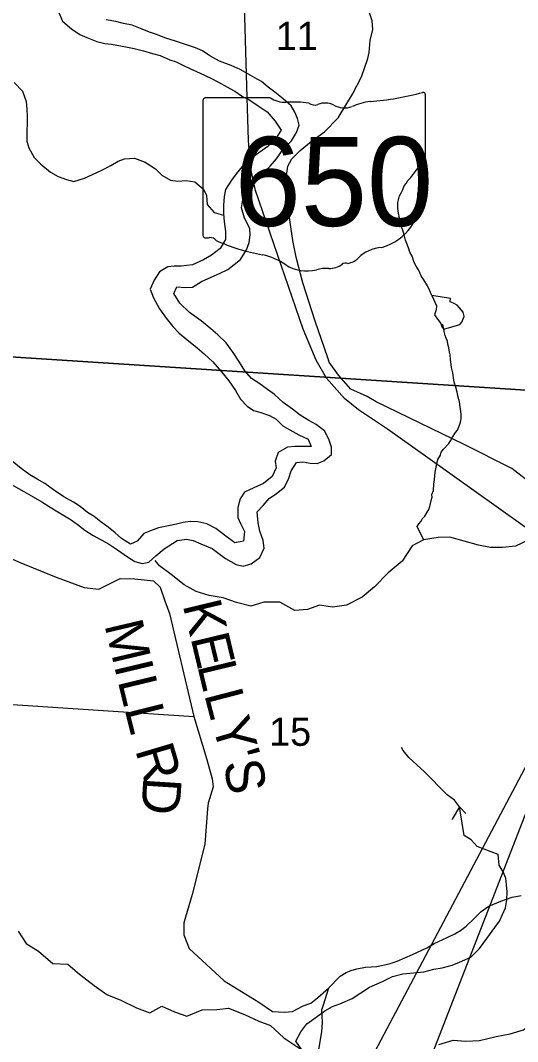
# Model space of a CAD drawing. Extents: x 0 to 34, y 0 to 22.
# Drawn here: x 4.467 to 5.204, y 16.547 to 18.059 of the extents above; entities that cross this region are included whole.
import ezdxf

# ---------------------------------------------------------------- set-up
doc = ezdxf.new("R2010")
doc.units = 0
for name, color, linetype in [('GM_X_County_Road', 7, 'Continuous'), ('GM_X_County_Road_Text', 7, 'Continuous'), ('GM_X_Minor_Lake', 7, 'Continuous'), ('GM_X_Minor_River', 7, 'Continuous'), ('GM_X_Rail_Line', 7, 'Continuous'), ('GM_X_Section', 7, 'Continuous'), ('GM_X_Section_Text', 7, 'Continuous'), ('GM_X_State_Location', 7, 'Continuous'), ('GM_X_State_Route', 7, 'Continuous'), ('GM_X_State_Shield', 7, 'Continuous'), ('GM_X_Township_Road', 7, 'Continuous'), ('SH_Text', 7, 'Continuous')]:
    doc.layers.add(name, color=color, linetype=linetype)

msp = doc.modelspace()

# ---------------------------------------------------------------- linework, layer by layer
at = {"layer": 'GM_X_County_Road'}
for points in [[(4.4211, 17.2763), (4.4677, 17.2559), (4.52, 17.2346), (4.5613, 17.2194), (4.5829, 17.2172), (4.6147, 17.2327), (4.6367, 17.2323), (4.664, 17.2294), (4.6741, 17.2201), (4.681, 17.1999), (4.6879, 17.181), (4.7218, 17.037)], [(4.7218, 17.037), (4.7239, 17.0284), (4.7432, 16.9648), (4.7511, 16.9362), (4.7525, 16.9242), (4.7451, 16.9004), (4.744, 16.892), (4.74, 16.8395), (4.7214, 16.765), (4.7091, 16.723), (4.7092, 16.7052), (4.7168, 16.685), (4.7689, 16.637), (4.82, 16.6055), (4.8404, 16.5917), (4.8582, 16.5905), (4.8701, 16.5915), (4.8858, 16.6), (4.8972, 16.604), (4.9072, 16.6121), (4.9234, 16.6264), (4.9408, 16.6439), (4.9497, 16.6494), (4.957, 16.6525), (4.9656, 16.6551), (4.9782, 16.6575), (4.995, 16.6585), (5.0134, 16.6623), (5.0251, 16.6664), (5.048, 16.676), (5.069, 16.686), (5.0799, 16.6925), (5.0992, 16.7015), (5.1108, 16.7066), (5.1192, 16.7118), (5.1273, 16.7181), (5.1394, 16.7296), (5.1496, 16.7396), (5.1608, 16.7478), (5.1787, 16.7551), (5.1954, 16.7608), (5.2091, 16.7635)]]:
    msp.add_lwpolyline(points, dxfattribs=at)
at = {"layer": 'GM_X_Minor_Lake'}
for points in [[(5.0764, 17.6517), (5.0834, 17.6367), (5.083, 17.6306), (5.0803, 17.6235), (5.0848, 17.617), (5.0897, 17.6105), (5.0915, 17.6055), (5.0942, 17.6022)], [(5.0942, 17.6022), (5.1181, 17.6088), (5.1211, 17.6122), (5.1246, 17.6209), (5.1231, 17.627), (5.1175, 17.6334), (5.1141, 17.6376), (5.1088, 17.6407), (5.1035, 17.6423), (5.1035, 17.643), (5.104, 17.6476), (5.0764, 17.6517)]]:
    msp.add_lwpolyline(points, dxfattribs=at)
at = {"layer": 'GM_X_Minor_River'}
for points in [[(4.5238, 18.0712), (4.5294, 18.0579), (4.5424, 18.0468), (4.5549, 18.0384), (4.5652, 18.0339)], [(4.8178, 17.3315), (4.8265, 17.341), (4.8353, 17.3512), (4.8463, 17.3588), (4.8584, 17.3683), (4.8645, 17.3816), (4.8683, 17.3923), (4.876, 17.4044), (4.8855, 17.4056), (4.8961, 17.4036), (4.9064, 17.4029), (4.9166, 17.4071), (4.928, 17.4165), (4.9277, 17.4272), (4.9246, 17.4378), (4.9178, 17.4511), (4.9053, 17.461), (4.8942, 17.4667), (4.8813, 17.4747), (4.8703, 17.4835), (4.8563, 17.4934), (4.8433, 17.5052), (4.8331, 17.5128), (4.8202, 17.5223), (4.8091, 17.5288), (4.7993, 17.5406), (4.7917, 17.5531), (4.7822, 17.5676), (4.7716, 17.5816), (4.7594, 17.5938), (4.7491, 17.6026), (4.7347, 17.6144), (4.7176, 17.6269), (4.7032, 17.6406), (4.6941, 17.6547), (4.6986, 17.6646), (4.7108, 17.6638), (4.7218, 17.6642), (4.7351, 17.6725), (4.7496, 17.679), (4.7621, 17.6843), (4.7743, 17.6903), (4.7929, 17.7052), (4.8021, 17.7196), (4.8059, 17.7302), (4.8074, 17.7416), (4.8066, 17.7511), (4.799, 17.7663), (4.7945, 17.7816), (4.7968, 17.7964), (4.8025, 17.8089), (4.8105, 17.8184), (4.8223, 17.8294), (4.8371, 17.8435), (4.8462, 17.8545), (4.8561, 17.8685), (4.8687, 17.8811), (4.8759, 17.8932), (4.8797, 17.9039), (4.8774, 17.9138), (4.8736, 17.9233), (4.868, 17.9328), (4.8562, 17.943), (4.844, 17.9529), (4.8341, 17.9602), (4.8243, 17.9689), (4.8144, 17.9743), (4.8041, 17.9803), (4.7927, 17.9864), (4.7791, 17.9925), (4.762, 17.999), (4.7475, 18.007), (4.7365, 18.0142), (4.7262, 18.0188), (4.7114, 18.0234), (4.6966, 18.0283), (4.6825, 18.0329), (4.6685, 18.0382), (4.6582, 18.042), (4.6472, 18.0462), (4.6324, 18.052), (4.6199, 18.0546), (4.6081, 18.0577), (4.594, 18.0603)], [(4.5652, 18.0339), (4.5804, 18.0278), (4.5921, 18.0251), (4.602, 18.024), (4.6153, 18.0217), (4.6256, 18.0198), (4.6355, 18.0175), (4.6495, 18.014), (4.6624, 18.0102), (4.6742, 18.0072), (4.6883, 18.0007), (4.6978, 17.9977), (4.7084, 17.9927), (4.7179, 17.9878), (4.7331, 17.9813), (4.7491, 17.9737), (4.7605, 17.968), (4.773, 17.9611), (4.7848, 17.9546), (4.7958, 17.9466), (4.8053, 17.9421), (4.8194, 17.9326), (4.8323, 17.9238), (4.8444, 17.9101), (4.8535, 17.8968), (4.8467, 17.8869), (4.8334, 17.8725), (4.8204, 17.863), (4.8083, 17.8546), (4.7953, 17.8429), (4.7866, 17.8322), (4.7798, 17.8227), (4.771, 17.8091), (4.7687, 17.7984), (4.7676, 17.7855), (4.7676, 17.7726), (4.7687, 17.7615), (4.771, 17.7467), (4.7706, 17.7349), (4.763, 17.7216), (4.75, 17.7118), (4.7382, 17.7046), (4.7219, 17.6974), (4.7052, 17.6951), (4.6949, 17.6951), (4.6854, 17.6943), (4.6729, 17.6868), (4.6649, 17.6746), (4.6592, 17.6613), (4.6641, 17.6484), (4.6728, 17.632), (4.6827, 17.6183), (4.6926, 17.6062), (4.7021, 17.5963), (4.7135, 17.5867), (4.7287, 17.5746), (4.7393, 17.5654), (4.7518, 17.5536), (4.7647, 17.5388), (4.7757, 17.5255), (4.7856, 17.511), (4.7928, 17.4985), (4.8027, 17.4878), (4.8122, 17.4814), (4.8217, 17.4791), (4.8358, 17.4741), (4.846, 17.4688), (4.8555, 17.4589), (4.8662, 17.4528), (4.8795, 17.4456), (4.8931, 17.4391), (4.8977, 17.4285), (4.8867, 17.4281), (4.8741, 17.4281), (4.8627, 17.4274), (4.849, 17.4194), (4.8445, 17.4065), (4.846, 17.3966), (4.8399, 17.3837), (4.827, 17.3734), (4.8129, 17.3673), (4.7988, 17.3609), (4.7924, 17.351), (4.7889, 17.3381), (4.7889, 17.3233), (4.7935, 17.3134), (4.7988, 17.3024), (4.7976, 17.2883), (4.7847, 17.2856), (4.7714, 17.2955), (4.7566, 17.307), (4.7429, 17.3138), (4.73, 17.3169), (4.719, 17.3173), (4.7083, 17.3157), (4.6981, 17.3135), (4.6863, 17.3108), (4.6715, 17.3078), (4.6597, 17.3036), (4.6498, 17.2994), (4.6399, 17.2881)], [(4.4575, 17.9675), (4.4699, 17.9545), (4.4755, 17.9393), (4.4762, 17.9279), (4.4769, 17.918), (4.4768, 17.9066), (4.4764, 17.8959), (4.4766, 17.8804), (4.4796, 17.8705), (4.4875, 17.8563), (4.4973, 17.8464), (4.5117, 17.8345), (4.5231, 17.828), (4.5352, 17.8237), (4.5462, 17.8206), (4.5618, 17.8258), (4.5736, 17.831), (4.5878, 17.8374), (4.6007, 17.8445), (4.6118, 17.8509), (4.6213, 17.8542), (4.6358, 17.8553), (4.6517, 17.8491), (4.6672, 17.8395), (4.6763, 17.8299), (4.6892, 17.8226), (4.7002, 17.8214), (4.7127, 17.822), (4.7253, 17.82), (4.7381, 17.8093), (4.7426, 17.7998), (4.7437, 17.7868), (4.7539, 17.7746), (4.7676, 17.7707)], [(5.0764, 17.6517), (5.0759, 17.653), (5.0733, 17.6587), (5.0699, 17.666), (5.0647, 17.6752), (5.061, 17.6801), (5.0591, 17.6843), (5.0566, 17.6901), (5.0532, 17.6951), (5.0502, 17.7008), (5.0473, 17.71), (5.044, 17.7161), (5.0418, 17.7226), (5.0396, 17.7287), (5.0373, 17.7336), (5.0355, 17.7416), (5.0337, 17.7485), (5.0322, 17.7523), (5.0308, 17.7592), (5.0286, 17.7668), (5.0272, 17.774), (5.0261, 17.7805), (5.0262, 17.7896), (5.0286, 17.7995), (5.0313, 17.804), (5.0336, 17.8089), (5.0356, 17.8142), (5.0391, 17.818), (5.0406, 17.8217), (5.0456, 17.8266), (5.0483, 17.8304), (5.056, 17.8405), (5.0598, 17.8409)], [(5.0641, 17.2907), (5.0548, 17.3098), (5.0571, 17.3136), (5.0606, 17.3177), (5.0629, 17.3215), (5.066, 17.3252), (5.0695, 17.3313), (5.0722, 17.335), (5.0734, 17.3396), (5.0754, 17.3483), (5.077, 17.3532), (5.0766, 17.3574), (5.079, 17.3634), (5.0795, 17.3725), (5.0803, 17.3794), (5.0812, 17.3904), (5.0824, 17.3953), (5.0832, 17.4002), (5.0856, 17.4093), (5.0894, 17.4153), (5.0902, 17.4199), (5.0937, 17.4244), (5.1018, 17.433), (5.1041, 17.4368), (5.1072, 17.4421), (5.1114, 17.4489), (5.1145, 17.4526), (5.1173, 17.4598), (5.1192, 17.4644), (5.12, 17.4693), (5.1201, 17.4757), (5.1194, 17.4799), (5.1187, 17.4872), (5.1173, 17.4944), (5.1155, 17.5013), (5.114, 17.5089), (5.1115, 17.518), (5.11, 17.5222), (5.1093, 17.5264), (5.1075, 17.5375), (5.1057, 17.5455), (5.105, 17.5496), (5.1043, 17.5573), (5.1037, 17.5641), (5.1026, 17.5679), (5.1015, 17.5744), (5.1004, 17.5797), (5.0997, 17.5843), (5.0975, 17.5885), (5.0964, 17.5927), (5.095, 17.5984), (5.0942, 17.6022), (5.0932, 17.6064), (5.0925, 17.6093)], [(4.6399, 17.2881), (4.63, 17.2835), (4.6167, 17.2919), (4.6072, 17.3006), (4.597, 17.309), (4.5863, 17.3166), (4.5761, 17.3246), (4.5662, 17.3307), (4.5556, 17.3394), (4.5457, 17.3459), (4.5312, 17.3539), (4.516, 17.3642), (4.5031, 17.3737), (4.4917, 17.3798), (4.4807, 17.3863), (4.4682, 17.3958), (4.4549, 17.4068)], [(4.456, 17.3706), (4.4719, 17.3618), (4.486, 17.3538), (4.4989, 17.3462), (4.511, 17.3386), (4.5224, 17.3317), (4.5323, 17.3257), (4.5422, 17.3199), (4.5528, 17.312), (4.5623, 17.3043), (4.5745, 17.2967), (4.5874, 17.2895), (4.5973, 17.2842), (4.6106, 17.2754), (4.6258, 17.2651), (4.6364, 17.2579), (4.6471, 17.2549), (4.6573, 17.2571), (4.6676, 17.2662), (4.6801, 17.2769), (4.6991, 17.289), (4.7128, 17.2913), (4.7227, 17.289), (4.7341, 17.2844), (4.7512, 17.2772), (4.7706, 17.2627), (4.7865, 17.2536), (4.7968, 17.2513), (4.809, 17.2547), (4.8219, 17.2642), (4.828, 17.2779), (4.8268, 17.2893), (4.8219, 17.303), (4.8193, 17.3151), (4.8178, 17.3315)], [(5.2183, 17.2893), (5.2004, 17.2807), (5.1811, 17.2789), (5.1633, 17.279), (5.1458, 17.2821), (5.1246, 17.2879), (5.1034, 17.2941), (5.086, 17.2935), (5.0644, 17.2902), (5.0472, 17.2811), (5.0327, 17.2584), (5.0117, 17.2411), (4.9915, 17.2207), (4.9732, 17.2052), (4.9503, 17.1936), (4.9295, 17.1903), (4.9101, 17.1934), (4.8923, 17.187), (4.8737, 17.1856), (4.8514, 17.1979), (4.8275, 17.1976), (4.8081, 17.192), (4.7873, 17.1975), (4.7672, 17.2044), (4.7468, 17.2079), (4.7275, 17.2137), (4.7097, 17.2237), (4.6901, 17.239), (4.6728, 17.2516), (4.6667, 17.2595)], [(5.1267, 16.8849), (5.1177, 16.8948), (5.1102, 16.9047), (5.0993, 16.9124), (5.0876, 16.9246), (5.0763, 16.9357), (5.0658, 16.9467), (5.0545, 16.9571), (5.0425, 16.9678), (5.0338, 16.9784), (5.0316, 16.9826)], [(5.1763, 16.8085), (5.1748, 16.8242), (5.1646, 16.8281), (5.154, 16.8323), (5.1438, 16.8362), (5.1348, 16.8461), (5.1246, 16.8522), (5.1177, 16.8948), (5.1066, 16.8766), (5.1066, 16.8759)], [(4.8838, 16.535), (4.875, 16.5478), (4.8825, 16.5615), (4.8912, 16.5732), (4.9049, 16.5831), (4.9181, 16.5926), (4.9294, 16.599), (4.9404, 16.6032), (4.9585, 16.6108), (4.9842, 16.6275), (5.0035, 16.6359), (5.0183, 16.6435), (5.0334, 16.6476), (5.0493, 16.6488), (5.0648, 16.6503), (5.0795, 16.6545), (5.0916, 16.6564), (5.1067, 16.6602), (5.1177, 16.6648), (5.1343, 16.6723), (5.1472, 16.6849), (5.1578, 16.6997), (5.1699, 16.716), (5.1767, 16.7255), (5.1857, 16.7452), (5.1876, 16.7569), (5.188, 16.7687), (5.1873, 16.7793), (5.1861, 16.7892), (5.1823, 16.7987), (5.1763, 16.8085)], [(4.4636, 16.7107), (4.4757, 16.6925), (4.4935, 16.6811), (4.515, 16.6628), (4.537, 16.6616), (4.5543, 16.6468), (4.5763, 16.63), (4.5951, 16.6171), (4.6159, 16.6087), (4.639, 16.5973), (4.6587, 16.5896), (4.6765, 16.5995), (4.695, 16.5911), (4.7136, 16.585), (4.7363, 16.5941), (4.7579, 16.5949), (4.7753, 16.5967), (4.7987, 16.5872), (4.8203, 16.5773), (4.8377, 16.5712), (4.857, 16.5526), (4.8838, 16.535)], [(5.0867, 16.5428), (5.1083, 16.5493), (5.1268, 16.5477), (5.1469, 16.5489), (5.1719, 16.5549), (5.1924, 16.5587), (5.2124, 16.5648), (5.2329, 16.5803), (5.2538, 16.6031), (5.2746, 16.6134), (5.2966, 16.605), (5.3151, 16.5917), (5.3359, 16.5802), (5.3506, 16.5601), (5.3691, 16.5399)]]:
    msp.add_lwpolyline(points, dxfattribs=at)
at = {"layer": 'GM_X_Rail_Line'}
msp.add_lwpolyline([(5.3195, 17.2344), (5.0671, 17.4139), (5.0106, 17.4538), (4.9679, 17.4828), (4.9471, 17.4992), (4.9206, 17.5297), (4.9053, 17.5563), (4.886, 17.6022), (4.8152, 17.8074), (4.808, 17.8412), (4.8048, 17.8814), (4.8031, 17.945), (4.7895, 18.4061), (4.7838, 18.542), (4.7798, 18.5718), (4.7742, 18.6177), (4.7589, 18.6998), (4.7275, 18.8672)], dxfattribs=at)
at = {"layer": 'GM_X_Section'}
for points in [[(4.4314, 18.5943), (5.4469, 18.529), (5.3838, 17.5009), (4.383, 17.5655)], [(4.383, 17.5655), (5.3838, 17.5009), (5.3178, 16.4777), (4.3194, 16.5337)]]:
    msp.add_lwpolyline(points, close=True, dxfattribs=at)
at = {"layer": 'GM_X_State_Route'}
msp.add_lwpolyline([(5.2191, 17.3772), (5.195, 17.3957), (5.1235, 17.4319), (4.9942, 17.4947), (4.9805, 17.5025), (4.9563, 17.513), (4.938, 17.5341), (4.9246, 17.5531), (4.9222, 17.5596), (4.9037, 17.6138), (4.8856, 17.6705), (4.8757, 17.7088), (4.8706, 17.7333), (4.862, 17.791), (4.8603, 17.8233), (4.8633, 17.8435), (4.869, 17.8544), (4.8813, 17.8667), (4.8978, 17.88), (4.9175, 17.8942), (4.9376, 17.9148), (4.9591, 17.9501), (4.9724, 17.9757), (4.9816, 18.0028), (4.9835, 18.0115), (4.9852, 18.0293), (4.9889, 18.0458), (4.988, 18.0586), (4.9788, 18.0861)], dxfattribs=at)
at = {"layer": 'GM_X_State_Shield'}
for p, q in [((5.067, 17.8446), (5.067, 17.9493)), ((4.7374, 17.9409), (4.7374, 17.7408)), ((4.8372, 17.9444), (4.7407, 17.9444)), ((5.067, 17.8447), (5.067, 17.8446))]:
    msp.add_line(p, q, dxfattribs=at)
for centre, major_axis, start_param, end_param in [((4.9496, 18.2172), (0.3495, 0), 4.814394, 5.042369), ((5.0633, 17.9497), (0.00367, 0), 6.141152, 7.989035), ((4.7412, 17.9413), (0.00382, 0), 1.712693, 3.28349), ((4.8602, 17.9676), (0.037, 0), 4.042523, 4.731795), ((4.8724, 17.832), (0.133, 0), 1.404758, 1.657858), ((4.9026, 17.9424), (0.0107, 0), 3.836095, 5.185415), ((4.9183, 17.9192), (0.0222, 0), 0.950623, 2.079405), ((4.947, 17.951), (0.0267, 0), 4.081561, 5.145723), ((4.9942, 17.8832), (0.0703, 0), 1.699011, 2.107814), ((5.0631, 17.8442), (0.00393, 0), 5.05454, 6.418171), ((5.0661, 17.8369), (0.00568, 0), 1.883978, 3.671073), ((5.03, 17.8237), (0.0341, 0), 5.934695, 6.695948), ((5.0801, 17.8008), (0.0248, 0), 2.387724, 3.262537), ((4.9692, 17.7875), (0.0874, 0), 5.101752, 6.440018), ((4.7412, 17.7404), (0.00385, 0), 3.00124, 4.508301), ((4.7418, 17.7608), (0.0294, 0), 4.665946, 4.897461), ((4.7478, 17.7292), (0.0106, 0), 0.519207, 1.627899), ((4.8816, 17.909), (0.2524, 0), 4.195997, 4.488961), ((5.006, 17.6846), (0.0479, 0), 1.647645, 2.488434), ((4.8064, 17.6509), (0.079, 0), 0.823519, 1.323587), ((4.9454, 17.7214), (0.0282, 0), 4.937069, 5.64225), ((4.8918, 17.7283), (0.0501, 0), 4.026481, 4.996735), ((4.9208, 17.6591), (0.0412, 0), 1.495662, 1.94098), ((4.9244, 17.7133), (0.0267, 0), 4.691044, 5.507374), ((4.9486, 17.6939), (0.00752, 0), 1.147584, 2.315152)]:
    msp.add_ellipse(centre, major_axis=major_axis, ratio=0.8, start_param=start_param, end_param=end_param, dxfattribs=at)
at = {"layer": 'GM_X_Township_Road'}
msp.add_line((4.3514, 17.0533), (4.7239, 17.0284), dxfattribs=at)
msp.add_lwpolyline([(4.9234, 16.6264), (4.9156, 16.6012), (4.9128, 16.5937), (4.9138, 16.5757), (4.9128, 16.5617), (4.9079, 16.5327), (4.9117, 16.5099), (4.9132, 16.5055), (4.9179, 16.4999), (4.9224, 16.497), (4.9362, 16.4952), (4.9495, 16.4952), (4.9521, 16.4936), (4.9547, 16.4913), (4.964, 16.4787), (4.9711, 16.4758), (4.9917, 16.4772), (5.0047, 16.475), (5.0105, 16.4708), (5.0204, 16.4599), (5.0984, 16.3092), (5.1017, 16.2936)], dxfattribs=at)
at = {"layer": 'SH_Text'}
msp.add_lwpolyline([(4.1319, 14.1), (4.1319, 14.9089), (5.3159, 17.1435)], close=True, dxfattribs=at)

# ---------------------------------------------------------------- texts
at = {"layer": 'GM_X_County_Road_Text'}
for s, rotation, p in [('K', 283.4743, (4.7071, 17.1939)), ('M', 283.3313, (4.5912, 17.1645)), ('E', 283.4692, (4.7188, 17.1453)), ('I', 283.3898, (4.6054, 17.1045)), ('L', 283.583, (4.7287, 17.1039)), ('L', 283.5846, (4.6109, 17.0816)), ('L', 284.6517, (4.739, 17.0614)), ('L', 284.1107, (4.621, 17.0397)), ('Y', 286.3844, (4.7502, 17.0185)), ('R', 286.544, (4.6366, 16.9791)), ("'", 286.2757, (4.7643, 16.9706)), ('S', 280.6232, (4.7675, 16.96)), ('D', 266.2854, (4.6493, 16.9396))]:
    msp.add_text(s, height=0.0568, rotation=rotation, dxfattribs=at).set_placement(p)
at = {"layer": 'GM_X_Section_Text'}
for s, p in [('11', (4.8454, 18.0154)), ('15', (4.8354, 16.9851))]:
    msp.add_text(s, height=0.04186, rotation=0, dxfattribs=at).set_placement(p)
at = {"layer": 'GM_X_State_Location'}
msp.add_text('650', height=0.000189, rotation=0, dxfattribs=at).set_placement((5.0487, 17.359))
for s in ['s', 'r']:
    msp.add_text(s, height=0.000189, dxfattribs=at).set_placement((5.1156, 17.3728))
at = {"layer": 'GM_X_State_Shield'}
msp.add_text('650', height=0.13184, dxfattribs=at).set_placement((4.7844, 17.7549))

doc.saveas('drawing.dxf')
